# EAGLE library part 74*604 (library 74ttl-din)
Octal 2-input MULTIPLEXED LATCH
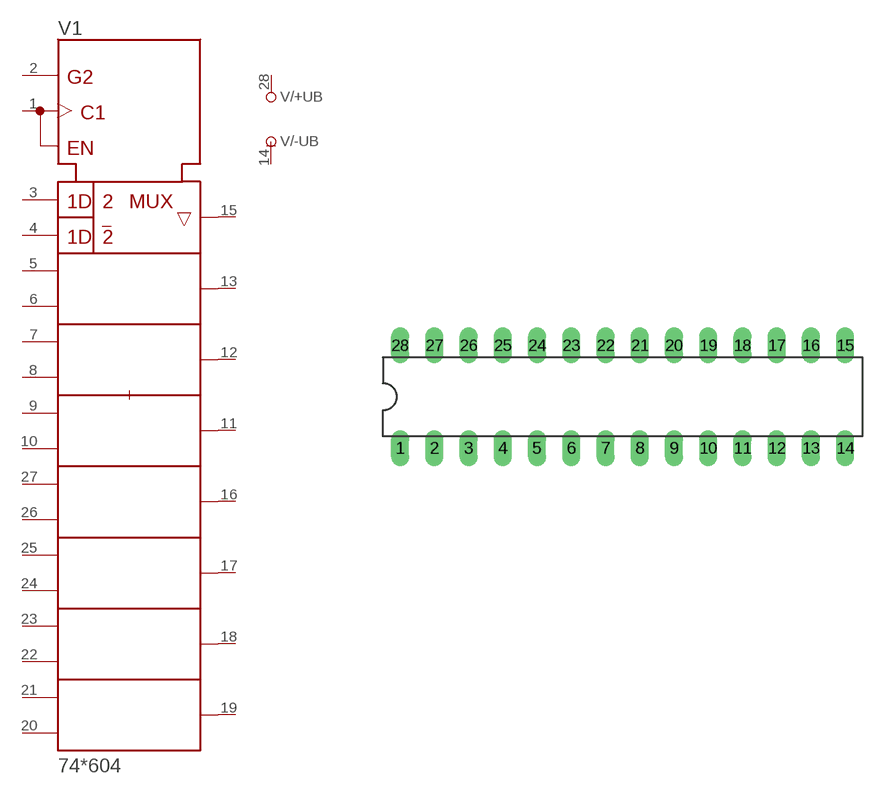
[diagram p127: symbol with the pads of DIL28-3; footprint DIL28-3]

Designator prefix V; gates /+UB=+UB /-UB=-UB 1=604

## 74604N  [DIL28-3]
1  1:CLK  in
2  1:SEL_A/B\  in
3  1:A1  in
4  1:B1  in
5  1:A2  in
6  1:B2  in
7  1:A3  in
8  1:B3  in
9  1:A4  in
10  1:B4  in
11  1:Y4  hiz
12  1:Y3  hiz
13  1:Y2  hiz
14  /-UB:-UB  pwr
15  1:Y1  hiz
16  1:Y5  hiz
17  1:Y6  hiz
18  1:Y7  hiz
19  1:Y8  hiz
20  1:B8  in
21  1:A8  in
22  1:B7  in
23  1:A7  in
24  1:B6  in
25  1:A6  in
26  1:B5  in
27  1:A5  in
28  /+UB:+UB  pwr

## Footprint DIL28-3 (pad centres in mm)
Dual In Line Package Small
drill 0.813 long: 1 -16.51,-3.81; 2 -13.97,-3.81; 3 -11.43,-3.81; 4 -8.89,-3.81; 5 -6.35,-3.81; 6 -3.81,-3.81; 7 -1.27,-3.81; 8 1.27,-3.81; 9 3.81,-3.81; 10 6.35,-3.81; 11 8.89,-3.81; 12 11.43,-3.81; 13 13.97,-3.81; 14 16.51,-3.81; 15 16.51,3.81; 16 13.97,3.81; 17 11.43,3.81; 18 8.89,3.81; 19 6.35,3.81; 20 3.81,3.81; 21 1.27,3.81; 22 -1.27,3.81; 23 -3.81,3.81; 24 -6.35,3.81; 25 -8.89,3.81; 26 -11.43,3.81; 27 -13.97,3.81; 28 -16.51,3.81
